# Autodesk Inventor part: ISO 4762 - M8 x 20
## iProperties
IsCustomPart: 0
Created: 2007-11
Part Number: ISO 4762 - M8 x 20
Material: Stainless Steel, 440C
Description: Hexagon Socket Head Cap Screw
Document SubType Name: Modeling
Standard: ISO 4762
Designer: CM
Standard Revision: Fourth edition 2004-03-01
Standards Organization: ISO
Language: en-US
Size Designation: M8 x 20
Categories: <MemberInstance><Categories><Category DisplayName="Fasteners" InternalName="e4da775c-781d-43d5-af7c-5136215cf5a6" Mnemonic="FSTN"><Category DisplayName="Bolts"
Density: 7.75 g/cm^3
Mass: 14.7692 g
Surface Area: 11.5903 cm^2
Volume: 1.9057 cm^3
Author: CM
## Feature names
1. Body [Revolution]
2. Slot [Extrusion]
3. Fillet1
4. Chamfer1
5. Fillet2
